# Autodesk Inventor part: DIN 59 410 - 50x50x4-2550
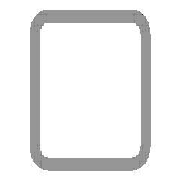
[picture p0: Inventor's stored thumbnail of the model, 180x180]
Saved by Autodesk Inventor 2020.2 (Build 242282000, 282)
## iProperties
Manager: www.cadconsulting.pl
Company: Fabian Stasiak CAD Consulting
IsCustomPart: 1
_CCFamilyMember: 40
_CCFamilyDisplayName: DIN 59410 (Kwadrat) - Rurki stalowe o przekroju kwadratowym formowane na gorąco
_FrameMemberDoc: Frame Member File
_Version: 15.0.0
_GetPNFromCC: 1
Created: 2015-01
Part Number: DIN 59 410 - 50x50x4-2550
Material: Stal, miękka
Description: Rurki stalowe o przekroju kwadratowym formowane na gorąco
Document SubType Name: Modellieren
Standard: DIN
Designer: F.Stasiak
Standards Organization: DIN
Language: pl-PL
Size Designation: 50x50x4
Categories: <MemberInstance><Categories><Category DisplayName="Kształtowniki konstrukcyjne" InternalName="089c4875-fa83-4c05-b084-43b9cc11f5ed" Mnemonic="GRDR"><CategoryPar
Stock Number: 50x50x4
Density: 7.85 g/cm^3
Appearance: Częściowo polerowana
Mass: 20313.7 g
Surface Area: 12959 cm^2
Volume: 2587.73 cm^3
Catalog Web Link: www.expertbooks.pl
G_W: 50,000 mm
G_H: 50,000 mm
G_L: 2550,000 mm
+FF09A0CC-BFA5-452C-9466-FACB79AE8C02+CUTDETAIL3: Wytnij
+8470243B-B4C6-4DC1-B0F6-61767A2AE017+CUTDETAIL4: Wytnij
Author: F.Stasiak
Subject: Zbiór ćwiczeń. Autodesk Inventor 2020. Kurs Professional
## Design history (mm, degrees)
node "Płaszczyzna początkowa"
node "Płaszczyzna końcowa"
sketch "Szkic1"
  geometry: L1 (-17, 25)-(17, 25); L2 (25, 17)-(25, -17); L3 (17, -25)-(-17, -25); L4 (-25, -17)-(-25, 17); L5 (-51.32, 0)-(51.32, 0) reference; L6 (0, -51.32)-(0, 51.32) reference; L7 (-17, 21)-(17, 21); L8 (21, 17)-(21, -17); L9 (17, -21)-(-17, -21); L10 (-21, -17)-(-21, 17); A1 r 8 centre (-17, 17) between (-17, 25) and (-25, 17); A2 r 8 centre (17, 17) between (25, 17) and (17, 25); A3 r 8 centre (17, -17) between (17, -25) and (25, -17); A4 r 8 centre (-17, -17) between (-25, -17) and (-17, -25); A5 r 4 centre (-17, 17) between (-17, 21) and (-21, 17); A6 r 4 centre (17, 17) between (21, 17) and (17, 21); A7 r 4 centre (17, -17) between (17, -21) and (21, -17); A8 r 4 centre (-17, -17) between (-21, -17) and (-17, -21); 3 further points
  constraints: 16 end point, 16 point on circle, 8 centre point, 8 tangent, 6 point on line, 4 parallel, 3 equal radius, 3 perpendicular, 1 horizontal, 7 other
  dimensions: "b" = 50 distance of point (-25, 25) point (25, 25); "msp_r" = 8 radius of A1 (= 2 x ParT); "d8" = 25 distance between parallel lines of L4 L6 (= d9); "d9" = 25 distance between parallel lines of L3 L5 (= 0.5 x b); "d10" = 4 distance between parallel lines of L3 L9 (= ParT)
extrude "Bryła" new body sketch "Szkic1" taper "d4" = 0 deg; stored distance "NLG" = 10
node "Driven Length"
  sketch "Sketch2"
    geometry: L1 (0, 0)-(10, 0) reference
    constraints: 2 end point, 1 horizontal
  workplane "Work Plane3"
  sketch "Sketch3"
    geometry: L1 (-2, -25)-(12, -25) reference; L2 (-2, 2525)-(12, 2525) reference
    dimensions: "d14" = 2550 distance between parallel lines of L1 L2 (derived)
node "Płaszczyzna konstrukcyjna6"
feature "Podział3"
node "Płaszczyzna konstrukcyjna7"
feature "Podział4"
body "Solid1"
other parameters: "ParT" = 4, "G_OFFSET_START" = 25 [user parameter; used in 1 equation term], "G_OFFSET_END" = 25 [user parameter; used in 1 equation term], "d11" = -25 (= -G_OFFSET_START), "d12" = 2525 (= G_OFFSET_END + B_L), "G_L" = 2550 (= d14) [user parameter], "d13" = 90 deg
